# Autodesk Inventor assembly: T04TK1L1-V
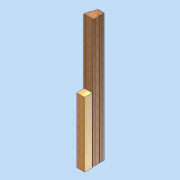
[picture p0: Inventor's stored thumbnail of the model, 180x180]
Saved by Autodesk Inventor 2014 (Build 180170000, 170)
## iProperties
Created: 2012-03
Part Number: T04TK1L1-V
Document SubType Name: Assembly
Designer: david.appleford
Description: 1w Threshold - 1 Lock 1 Lug
Mass: 4706 g
Surface Area: 5933.15 cm^2
Volume: 10695.5 cm^3
Density: 0.44 g/cm^3
Cost Center: £36.00
Justset: False
Author: david.appleford
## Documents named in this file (3)
- C:\Documents and Settings\john.everitt\Local Settings\My Documents\Vault\Production MkII\VIRTUAL ELEMENTS\Virtual Doors\Door Furniture\T04TK1L1V.iam
- C:\Documents and Settings\john.everitt\Local Settings\My Documents\Vault\Production MkII\VIRTUAL ELEMENTS\Virtual Doors\T04TK1V.ipt
- C:\Documents and Settings\john.everitt\Local Settings\My Documents\Vault\Production MkII\VIRTUAL ELEMENTS\Virtual Lugs\Superceded Lugs\LA02C3V.ipt
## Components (2 placed, 2 different names)
1. T04TK1V:1 — Mate:1, Flush:1, Flush:2
2. LA02C3V:1 — Mate:1, Flush:1, Flush:2
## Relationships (3: Flush 2, Mate 1)
- Mate:1: T04TK1V:1 ↔ LA02C3V:1
- Flush:1: T04TK1V:1 ↔ LA02C3V:1
- Flush:2: T04TK1V:1 ↔ LA02C3V:1
